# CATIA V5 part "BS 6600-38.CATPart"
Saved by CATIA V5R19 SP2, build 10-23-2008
Part number: BS 6600-38
Bounding box of the stored display mesh (mm): x -59.975 to 59.975, y -59.975 to 59.975, z 0 to 151
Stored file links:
  C:\Users\Bora\Desktop\3D Katı model\BS serisi\BS 6600\BS 6600-38.CATPart
  C:\Program Files\Dassault Systemes\B19\intel_a\reffiles\standard\MetricThickPitch.txt
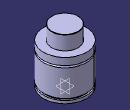
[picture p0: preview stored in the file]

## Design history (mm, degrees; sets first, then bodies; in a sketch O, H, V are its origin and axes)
Body1 (main body)
  Sketch1 on yz-plane, origin (0, 0, 0), H (0, 1, 0), V (0, 0, 1)
    point P1 (60, 92)
    point P2 (60, 87)
    point P3 (60, 92)
    point P7 (37.5, 150)
    point P9 (37.5, 150)
    point P14 (60, 87)
    arc A1 centre (60, 89.5) radius 2.5 from (60, 92) to (60, 87) ccw
    line L1 (60, 92) -> (60, 112)
    line L2 (60, 0) -> (60, 8)
    arc A2 centre (36.5, 150) radius 1 from (37.5, 150) to (36.5, 151) ccw
    line L3 (37.5, 150) -> (37.5, 112)
    line L4 (56, 13) -> (56, 8)
    line L5 (60, 13) -> (60, 87)
    line L6 (36.5, 151) -> (0, 151)
    point P15 (0, 151)
    line L7 (37.5, 112) -> (60, 112)
    line L8 (0, 0) -> (60, 0)
    line L9 (56, 13) -> (60, 13)
    line L10 (56, 8) -> (60, 8)
    coincidence: P15 V, P1 P3, P2 P14, P7 P9
    tangency: L6 A2
    horizontal: L7 H, L8 H, L9 H, L10 H
  Shaft1: profile Sketch1, axis Sketch1.V, angle 360
  Sketch2 on face of Shaft1 from Sketch1.L8, origin (0, 0, 0), H (1, 0, 0), V (0, -1, 0)
    point P1 (40, 0)
    distance P1 V = 40
  Hole1: placed by Sketch2, at (40, 0, 0) direction (0, 0, 1), diameter 8.376, depth 8, threaded "M10", thread diameter 10, thread depth 8, pitch 1.5
  CircPattern1: of Hole1, instances 4, angular step 90, axis from xy-plane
